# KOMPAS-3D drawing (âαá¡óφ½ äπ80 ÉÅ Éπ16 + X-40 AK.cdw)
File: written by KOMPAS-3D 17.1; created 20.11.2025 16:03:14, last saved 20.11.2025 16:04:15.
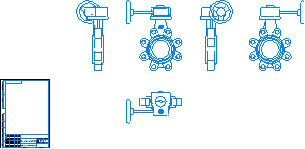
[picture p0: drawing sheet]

Sheet 1: A4, portrait

Title block, sheet 1: name: Гранвэл Ду80; material: Сталь 10  ГОСТ 1050-88; mass: 8,41; sheets: 1; sheet format: A4

Views: Вид 1, Спереди, Проекционный вид 2, Проекционный вид 3, Проекционный вид 4, Проекционный вид 5
Referenced files in \\adlc.lan\data\АДЛ_ПКД\3D-модели\ADL production\Дисковые поворотные затворы ГРАНВЭЛ\с резьбовыми проушинами с китайским редуктором Ру 16\KOMPAS 3D\: Гранвэл Ду80 РП Ру16 + X-40 AK.m3d
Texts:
  Andrey
  АДЛ
Dimensions and other numbers on the sheet: 1:1; 1; 8,41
